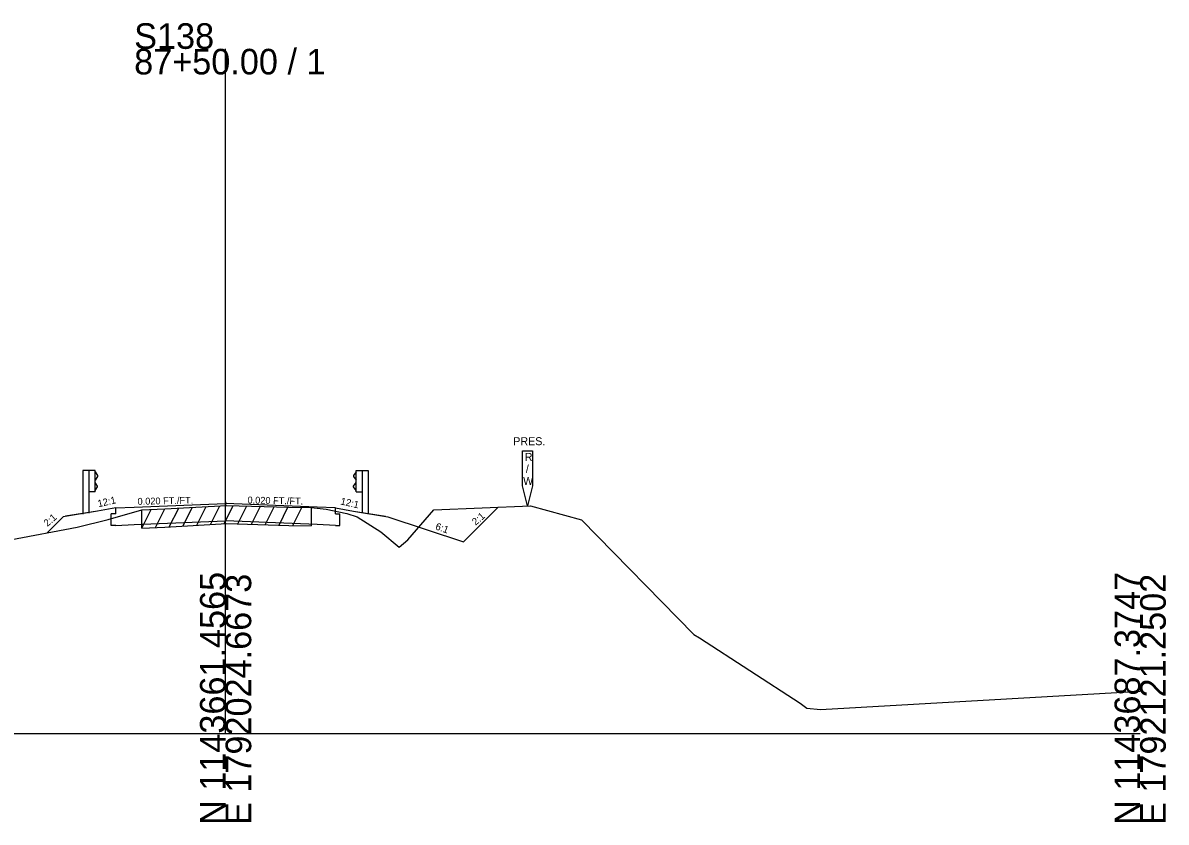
# Model space of a CAD drawing. Extents: x -26 to 1203, y -10 to 19606.
# Drawn here: x 77.8 to 202.8, y 14990.3 to 15077.8 of the extents above; entities that cross this region are included whole.
import ezdxf

# ---------------------------------------------------------------- set-up
doc = ezdxf.new("R2010")
doc.units = 0
for name, color, linetype in [('RD_EX_Driveway', 7, 'Continuous'), ('RD_GPK_XS_Cell', 7, 'Continuous'), ('RD_XS_Base', 7, 'Continuous'), ('RD_XS_EarthShd', 7, 'Continuous'), ('RD_XS_ExGround', 7, 'Continuous'), ('RD_XS_ExPaveRet', 7, 'Continuous'), ('RD_XS_ExRW', 7, 'Continuous'), ('RD_XS_GR', 7, 'Continuous'), ('RD_XS_Pave', 7, 'Continuous'), ('RD_XS_TX_Slope', 7, 'Continuous')]:
    doc.layers.add(name, color=color, linetype=linetype)

msp = doc.modelspace()

# ---------------------------------------------------------------- linework, layer by layer
at = {"layer": 'RD_GPK_XS_Cell'}
for p, q in [((100, 15000), (100, 15074.92)), ((0, 15000), (100, 15000)), ((100, 15000), (200, 15000))]:
    msp.add_line(p, q, dxfattribs=at)
at = {"layer": 'RD_XS_Base'}
for p, q in [((88, 15024.05), (88, 15024.69)), ((112, 15024.05), (112, 15024.69)), ((88, 15024.05), (87.5, 15024.03)), ((87.5, 15022.76), (87.5, 15024.03)), ((112, 15024.05), (112.5, 15024.03)), ((112.5, 15022.76), (112.5, 15024.03)), ((88, 15022.78), (87.5, 15022.76)), ((88, 15022.78), (90, 15022.86)), ((90, 15022.86), (100, 15023.28)), ((110, 15022.86), (100, 15023.28)), ((112, 15022.78), (110, 15022.86)), ((112, 15022.78), (112.5, 15022.76))]:
    msp.add_line(p, q, dxfattribs=at)
at = {"layer": 'RD_XS_EarthShd'}
for p, q in [((88, 15024.69), (86, 15024.35)), ((112, 15024.69), (114, 15024.35)), ((126, 15020.98), (129.79, 15024.77)), ((80.5, 15021.98), (82.25, 15023.73)), ((86, 15024.35), (82.25, 15023.73)), ((86, 15024.35), (82.5, 15023.77)), ((114, 15024.35), (117.5, 15023.77)), ((114, 15024.35), (117.75, 15023.73)), ((117.75, 15023.73), (126, 15020.98))]:
    msp.add_line(p, q, dxfattribs=at)
at = {"layer": 'RD_XS_ExGround'}
msp.add_lwpolyline([(76.43, 15021.2), (83.76, 15022.6), (87.17, 15023.43), (90.84, 15024.47), (93.36, 15024.59), (100.15, 15024.97), (106.91, 15024.78), (109.36, 15024.72), (111, 15024.54), (113.27, 15024.07), (114.39, 15023.7), (116.98, 15022.09), (118.96, 15020.4), (119.94, 15021.2), (122.76, 15024.48), (133.33, 15024.92), (138.9, 15023.39), (151.18, 15010.84), (151.83, 15010.48), (162.81, 15003.34), (163.56, 15002.78), (165.06, 15002.62), (200, 15004.64)], dxfattribs=at)
at = {"layer": 'RD_XS_ExPaveRet'}
for p, q in [((93.84, 15022.62), (94.87, 15024.67)), ((95.34, 15022.7), (96.37, 15024.76)), ((96.84, 15022.79), (97.87, 15024.84)), ((98.34, 15022.87), (99.37, 15024.93)), ((99.84, 15022.96), (100.84, 15024.95)), ((101.34, 15022.94), (102.32, 15024.91)), ((102.84, 15022.9), (103.82, 15024.87)), ((104.34, 15022.85), (105.32, 15024.82)), ((105.84, 15022.81), (106.82, 15024.78)), ((107.34, 15022.77), (108.32, 15024.74)), ((109.36, 15024.72), (109.36, 15022.72)), ((90.84, 15022.47), (91.86, 15024.52)), ((90.84, 15022.47), (90.84, 15024.47)), ((92.34, 15022.54), (93.36, 15024.59)), ((90.84, 15022.47), (93.36, 15022.59)), ((93.36, 15022.59), (100.15, 15022.97)), ((100.15, 15022.97), (106.91, 15022.78)), ((106.91, 15022.78), (109.36, 15022.72))]:
    msp.add_line(p, q, dxfattribs=at)
at = {"layer": 'RD_XS_ExRW'}
msp.add_lwpolyline([(132.45, 15030.92), (133.55, 15030.92), (133.55, 15027.09), (133, 15024.91), (132.45, 15027.09)], close=True, dxfattribs=at)
at = {"layer": 'RD_XS_GR'}
for p, q in [((84.4, 15028.77), (84.4, 15024)), ((85.06, 15028.77), (84.4, 15028.77)), ((85.06, 15028.77), (85.06, 15024.11)), ((85.73, 15028.77), (85.06, 15028.77)), ((85.73, 15026.44), (85.73, 15028.77)), ((85.73, 15028.62), (86, 15028.22)), ((114.27, 15028.62), (114, 15028.22)), ((114.27, 15026.44), (114.27, 15028.77)), ((114.27, 15028.77), (114.94, 15028.77)), ((114.94, 15028.77), (114.94, 15024.11)), ((114.94, 15028.77), (115.6, 15028.77)), ((115.6, 15028.77), (115.6, 15024)), ((86, 15028.12), (85.73, 15027.72)), ((86, 15027.08), (85.73, 15027.48)), ((86, 15028.22), (86, 15028.12)), ((114, 15028.22), (114, 15028.12)), ((114, 15028.12), (114.27, 15027.72)), ((114, 15027.08), (114.27, 15027.48)), ((85.73, 15026.44), (85.06, 15026.44)), ((85.73, 15026.58), (86, 15026.98)), ((86, 15026.98), (86, 15027.08)), ((114, 15026.98), (114, 15027.08)), ((114.27, 15026.58), (114, 15026.98)), ((114.27, 15026.44), (114.94, 15026.44))]:
    msp.add_line(p, q, dxfattribs=at)
at = {"layer": 'RD_XS_Pave'}
for p, q in [((88, 15024.69), (90, 15024.77)), ((90, 15024.77), (100, 15025.18)), ((110, 15024.77), (100, 15025.18)), ((112, 15024.69), (110, 15024.77))]:
    msp.add_line(p, q, dxfattribs=at)

# ---------------------------------------------------------------- texts
at = {"layer": 'RD_EX_Driveway'}
msp.add_text('541.48', height=0.0975, rotation=90, dxfattribs=at).set_placement((100.1, 15024.97))
at = {"layer": 'RD_GPK_XS_Cell'}
for s, p in [('S138', (90, 15074.92)), ('87+50.00 / 1', (90, 15072.12))]:
    msp.add_text(s, height=2.8, dxfattribs=at).set_placement(p)
for s, p in [('N 1143661.4565', (100, 14990)), ('E 1792024.6673', (102.8, 14990)), ('N 1143687.3747', (200, 14990)), ('E 1792121.2502', (202.8, 14990))]:
    msp.add_text(s, height=2.8, rotation=90, dxfattribs=at).set_placement(p)
at = {"layer": 'RD_XS_ExRW'}
for s, p in [('PRES.', (131.45, 15031.55)), ('R', (132.71, 15029.83)), ('/', (132.83, 15028.52)), ('W', (132.53, 15027.21))]:
    msp.add_text(s, height=0.875, dxfattribs=at).set_placement(p)
at = {"layer": 'RD_XS_TX_Slope'}
for s, height, rotation, p in [('0.020 FT./FT.', 0.7518, 358.8084, (102.39, 15025.18)), ('12:1', 0.778, 12.7511, (86.1, 15024.76)), ('0.020 FT./FT.', 0.7518, 1.1916, (90.38, 15025.03)), ('12:1', 0.778, 347.2489, (112.51, 15025.08)), ('2:1', 0.778, 40.6589, (80.51, 15022.6)), ('2:1', 0.778, 40.6589, (127.34, 15022.74)), ('6:1', 0.778, 340.6018, (122.87, 15022.36))]:
    msp.add_text(s, height=height, rotation=rotation, dxfattribs=at).set_placement(p)

doc.saveas('drawing.dxf')
